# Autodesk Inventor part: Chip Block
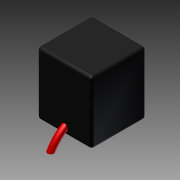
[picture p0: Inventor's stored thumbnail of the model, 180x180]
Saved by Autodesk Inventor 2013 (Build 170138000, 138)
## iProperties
Company: Autodesk Inc.
Created: 2005-12
Part Number: Chip Block
Document SubType Name: Modeling
Designer: Autodesk Inc.
Density: 1 g/cm^3
Mass: 1.15042 g
Surface Area: 6.57483 cm^2
Volume: 1.15042 cm^3
Material: Allgemein
Title: Personal Computer
Author: Autodesk Inc.
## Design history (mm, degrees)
sketch "Sketch1"
  geometry: L1 (0, 7)-(0, -7) reference; L2 (-7, 0)-(7, 0) reference; L3 (-5, 5)-(5, 5); L4 (5, 5)-(5, -5); L5 (5, -5)-(-5, -5); L6 (-5, -5)-(-5, 5)
  constraints: 8 end point, 2 parallel, 2 perpendicular, 1 horizontal, 2 other
  dimensions: "d0" = 10 distance of L3.start L3.end
extrude "Extrusion1" new body sketch "Sketch1" distance "d1" = 11.5; taper "d2" = 0 deg
sketch "Sketch2"
  geometry: L1 (-9.713, -1.5)-(9.943, -1.5); L2 (0, 14.855)-(0, -8.632) reference; L3 (5, 0)-(-5, 0) reference; L4 (-3.361, 1.942)-(3.888, 1.942); L5 (5, 0)-(5, 11.5) reference; L6 (-5, 0)-(-5, 11.5) reference; A1 r 6.171 centre (1.202, -3.614) between (7, -1.5) and (3.888, 1.942); A2 r 7.641 centre (-0.858, -5.277) between (-3.361, 1.942) and (-7.5, -1.5)
  constraints: 4 end point, 4 point on circle, 2 centre point, 2 point on line, 1 horizontal, 1 parallel
  dimensions: "d3" = 1.5 distance between parallel lines of L1 L3; "d4" = 2 distance from line of L5 A1.start; "d5" = 2.5 distance from line of L6 A2.end
workplane "Work Plane1"
sweep "Sweep1" dims "d8" = 0
fillet "Fillet1" dims "d9" = 0.5
body "Solid1"
sketch "Sketch4"
  geometry: C1 r 0.6 at (2.213, 0); 1 further point
  constraints: 1 centre point, 1 coincident
  dimensions: "d7" = 1.2 diameter of C1
other parameters: "d6" = 90 deg
